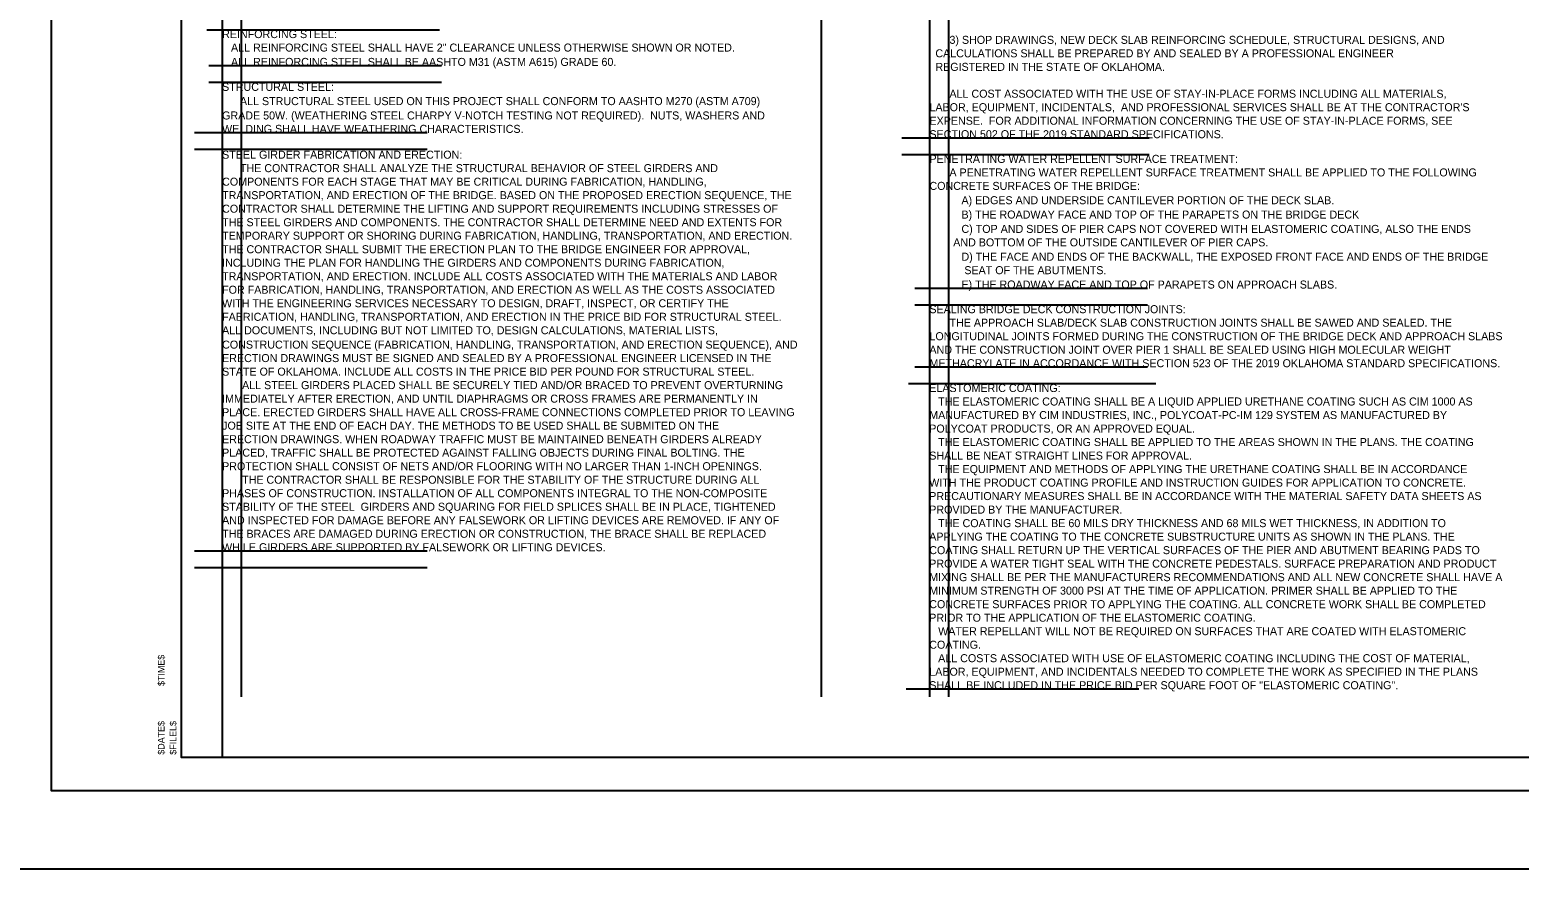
# Model space of a CAD drawing. Extents: x 12306 to 12361.5, y 578.9 to 640.4.
# Drawn here: x 12317.67 to 12340.01, y 612.91 to 625.5 of the extents above; entities that cross this region are included whole.
import ezdxf

# ---------------------------------------------------------------- set-up
doc = ezdxf.new("R2010")
doc.units = 0
for name, color, linetype in [('SHT_Plot_Shape_Full', 7, 'Continuous'), ('SHT_Plot_Shape_Half', 7, 'Continuous'), ('SHT_Plot_Stamp', 7, 'Continuous'), ('SHT_Sheet_Border', 7, 'Continuous'), ('T', 7, 'Continuous')]:
    doc.layers.add(name, color=color, linetype=linetype)

# ---------------------------------------------------------------- blocks, each defined once
blk = doc.blocks.new('Stamp_Plot_Stamp')
at = {"layer": 'SHT_Plot_Stamp'}
for s, p in [('$TIME$', (8.01, 7.43)), ('$DATE$', (8.01, 2.56)), ('$FILEL$', (8.85, 2.56))]:
    blk.add_text(s, height=0.472, rotation=90, dxfattribs=at).set_placement(p)

msp = doc.modelspace()

# ---------------------------------------------------------------- linework, layer by layer
at = {"layer": 'Defpoints'}
for p, q in [((12320.557, 635.145), (12320.557, 614.587)), ((12320.841, 635.145), (12320.841, 615.495)), ((12329.542, 635.145), (12329.542, 615.495)), ((12331.165, 635.145), (12331.165, 615.495)), ((12331.45, 635.145), (12331.45, 615.495)), ((12323.819, 625.494), (12320.33, 625.494)), ((12323.847, 624.957), (12320.358, 624.957)), ((12323.847, 624.707), (12320.358, 624.707)), ((12323.633, 623.953), (12320.144, 623.953)), ((12334.242, 623.873), (12330.752, 623.873)), ((12334.458, 623.873), (12330.969, 623.873)), ((12323.633, 623.703), (12320.144, 623.703)), ((12334.242, 623.623), (12330.752, 623.623)), ((12334.458, 623.623), (12330.969, 623.623)), ((12334.436, 621.619), (12330.946, 621.619)), ((12334.436, 621.369), (12330.946, 621.369)), ((12334.436, 620.439), (12330.946, 620.439)), ((12334.34, 620.189), (12330.85, 620.189)), ((12334.436, 620.189), (12330.946, 620.189)), ((12334.562, 620.189), (12331.072, 620.189)), ((12323.633, 617.68), (12320.144, 617.68)), ((12323.633, 617.43), (12320.144, 617.43)), ((12334.307, 615.611), (12330.817, 615.611))]:
    msp.add_line(p, q, dxfattribs=at)
at = {"layer": 'SHT_Plot_Shape_Full'}
msp.add_lwpolyline([(12316.36, 636.912), (12352.36, 636.912), (12352.36, 612.912), (12316.36, 612.912)], close=True, dxfattribs=at)
at = {"layer": 'SHT_Plot_Shape_Half'}
msp.add_lwpolyline([(12317.998, 636.087), (12351.998, 636.087), (12351.998, 614.087), (12317.998, 614.087)], close=True, dxfattribs=at)
at = {"layer": 'SHT_Sheet_Border'}
msp.add_lwpolyline([(12351.448, 614.587), (12319.948, 614.587), (12319.948, 635.587), (12351.448, 635.587)], close=True, dxfattribs=at)

# ---------------------------------------------------------------- block references
at = {"layer": 'SHT_Plot_Stamp', "xscale": 0.21166666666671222, "yscale": 0.21166666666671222}
msp.add_blockref('Stamp_Plot_Stamp', (12317.998, 614.087), dxfattribs=at)

# ---------------------------------------------------------------- texts
at = {"layer": 'T'}
for s, p in [('REINFORCING STEEL:', (12320.557, 625.374)), ('   ALL REINFORCING STEEL SHALL HAVE 2" CLEARANCE UNLESS OTHERWISE SHOWN OR NOTED.', (12320.557, 625.172)), ('3) SHOP DRAWINGS, NEW DECK SLAB REINFORCING SCHEDULE, STRUCTURAL DESIGNS, AND', (12331.465, 625.288)), ('   ALL REINFORCING STEEL SHALL BE AASHTO M31 (ASTM A615) GRADE 60.', (12320.557, 624.957)), ('  CALCULATIONS SHALL BE PREPARED BY AND SEALED BY A PROFESSIONAL ENGINEER', (12331.165, 625.086)), ('  REGISTERED IN THE STATE OF OKLAHOMA.', (12331.165, 624.883)), ('STRUCTURAL STEEL:', (12320.557, 624.583)), ('ALL COST ASSOCIATED WITH THE USE OF STAY-IN-PLACE FORMS INCLUDING ALL MATERIALS, ', (12331.465, 624.48)), ('      ALL STRUCTURAL STEEL USED ON THIS PROJECT SHALL CONFORM TO AASHTO M270 (ASTM A709) ', (12320.557, 624.369)), ("LABOR, EQUIPMENT, INCIDENTALS,  AND PROFESSIONAL SERVICES SHALL BE AT THE CONTRACTOR'S ", (12331.165, 624.278)), ('GRADE 50W. (WEATHERING STEEL CHARPY V-NOTCH TESTING NOT REQUIRED).  NUTS, WASHERS AND ', (12320.557, 624.154)), ('EXPENSE.  FOR ADDITIONAL INFORMATION CONCERNING THE USE OF STAY-IN-PLACE FORMS, SEE ', (12331.165, 624.075)), ('WELDING SHALL HAVE WEATHERING CHARACTERISTICS.', (12320.557, 623.953)), ('SECTION 502 OF THE 2019 STANDARD SPECIFICATIONS.', (12331.165, 623.873)), ('STEEL GIRDER FABRICATION AND ERECTION:', (12320.557, 623.566)), ('      THE CONTRACTOR SHALL ANALYZE THE STRUCTURAL BEHAVIOR OF STEEL GIRDERS AND ', (12320.557, 623.364)), ('PENETRATING WATER REPELLENT SURFACE TREATMENT:', (12331.165, 623.503)), ('COMPONENTS FOR EACH STAGE THAT MAY BE CRITICAL DURING FABRICATION, HANDLING, ', (12320.557, 623.161)), ('CONCRETE SURFACES OF THE BRIDGE:', (12331.165, 623.098)), ('A PENETRATING WATER REPELLENT SURFACE TREATMENT SHALL BE APPLIED TO THE FOLLOWING ', (12331.465, 623.3)), ('TRANSPORTATION, AND ERECTION OF THE BRIDGE. BASED ON THE PROPOSED ERECTION SEQUENCE, THE ', (12320.557, 622.959)), ('A) EDGES AND UNDERSIDE CANTILEVER PORTION OF THE DECK SLAB.', (12331.645, 622.883)), ('CONTRACTOR SHALL DETERMINE THE LIFTING AND SUPPORT REQUIREMENTS INCLUDING STRESSES OF ', (12320.557, 622.756)), ('B) THE ROADWAY FACE AND TOP OF THE PARAPETS ON THE BRIDGE DECK', (12331.645, 622.668)), ('THE STEEL GIRDERS AND COMPONENTS. THE CONTRACTOR SHALL DETERMINE NEED AND EXTENTS FOR ', (12320.557, 622.553)), ('C) TOP AND SIDES OF PIER CAPS NOT COVERED WITH ELASTOMERIC COATING, ALSO THE ENDS ', (12331.645, 622.453)), ('TEMPORARY SUPPORT OR SHORING DURING FABRICATION, HANDLING, TRANSPORTATION, AND ERECTION. ', (12320.557, 622.351)), ('        AND BOTTOM OF THE OUTSIDE CANTILEVER OF PIER CAPS.', (12331.165, 622.251)), ('THE CONTRACTOR SHALL SUBMIT THE ERECTION PLAN TO THE BRIDGE ENGINEER FOR APPROVAL, ', (12320.557, 622.148)), ('D) THE FACE AND ENDS OF THE BACKWALL, THE EXPOSED FRONT FACE AND ENDS OF THE BRIDGE    ', (12331.645, 622.036)), ('TRANSPORTATION, AND ERECTION. INCLUDE ALL COSTS ASSOCIATED WITH THE MATERIALS AND LABOR ', (12320.557, 621.743)), ('INCLUDING THE PLAN FOR HANDLING THE GIRDERS AND COMPONENTS DURING FABRICATION, ', (12320.557, 621.946)), ('     SEAT OF THE ABUTMENTS.', (12331.465, 621.834)), ('FOR FABRICATION, HANDLING, TRANSPORTATION, AND ERECTION AS WELL AS THE COSTS ASSOCIATED ', (12320.557, 621.541)), ('E) THE ROADWAY FACE AND TOP OF PARAPETS ON APPROACH SLABS.', (12331.645, 621.619)), ('WITH THE ENGINEERING SERVICES NECESSARY TO DESIGN, DRAFT, INSPECT, OR CERTIFY THE ', (12320.557, 621.338)), ('FABRICATION, HANDLING, TRANSPORTATION, AND ERECTION IN THE PRICE BID FOR STRUCTURAL STEEL. ', (12320.557, 621.135)), ('SEALING BRIDGE DECK CONSTRUCTION JOINTS:', (12331.165, 621.249)), ('ALL DOCUMENTS, INCLUDING BUT NOT LIMITED TO, DESIGN CALCULATIONS, MATERIAL LISTS, ', (12320.557, 620.933)), ('THE APPROACH SLAB/DECK SLAB CONSTRUCTION JOINTS SHALL BE SAWED AND SEALED. THE ', (12331.465, 621.047)), ('CONSTRUCTION SEQUENCE (FABRICATION, HANDLING, TRANSPORTATION, AND ERECTION SEQUENCE), AND ', (12320.557, 620.718)), ('AND THE CONSTRUCTION JOINT OVER PIER 1 SHALL BE SEALED USING HIGH MOLECULAR WEIGHT ', (12331.165, 620.641)), ('LONGITUDINAL JOINTS FORMED DURING THE CONSTRUCTION OF THE BRIDGE DECK AND APPROACH SLABS ', (12331.165, 620.844)), ('ERECTION DRAWINGS MUST BE SIGNED AND SEALED BY A PROFESSIONAL ENGINEER LICENSED IN THE ', (12320.557, 620.516)), ('METHACRYLATE IN ACCORDANCE WITH SECTION 523 OF THE 2019 OKLAHOMA STANDARD SPECIFICATIONS.', (12331.165, 620.439)), ('STATE OF OKLAHOMA. INCLUDE ALL COSTS IN THE PRICE BID PER POUND FOR STRUCTURAL STEEL.', (12320.557, 620.313)), ('ALL STEEL GIRDERS PLACED SHALL BE SECURELY TIED AND/OR BRACED TO PREVENT OVERTURNING ', (12320.857, 620.11)), ('ELASTOMERIC COATING:', (12331.162, 620.067)), ('IMMEDIATELY AFTER ERECTION, AND UNTIL DIAPHRAGMS OR CROSS FRAMES ARE PERMANENTLY IN ', (12320.557, 619.908)), ('   THE ELASTOMERIC COATING SHALL BE A LIQUID APPLIED URETHANE COATING SUCH AS CIM 1000 AS ', (12331.162, 619.865)), ('PLACE. ERECTED GIRDERS SHALL HAVE ALL CROSS-FRAME CONNECTIONS COMPLETED PRIOR TO LEAVING ', (12320.557, 619.705)), ('MANUFACTURED BY CIM INDUSTRIES, INC., POLYCOAT-PC-IM 129 SYSTEM AS MANUFACTURED BY ', (12331.162, 619.662)), ('JOB SITE AT THE END OF EACH DAY. THE METHODS TO BE USED SHALL BE SUBMITED ON THE ', (12320.557, 619.503)), ('ERECTION DRAWINGS. WHEN ROADWAY TRAFFIC MUST BE MAINTAINED BENEATH GIRDERS ALREADY ', (12320.557, 619.3)), ('POLYCOAT PRODUCTS, OR AN APPROVED EQUAL.', (12331.162, 619.459)), ('PLACED, TRAFFIC SHALL BE PROTECTED AGAINST FALLING OBJECTS DURING FINAL BOLTING. THE ', (12320.557, 619.098)), ('   THE ELASTOMERIC COATING SHALL BE APPLIED TO THE AREAS SHOWN IN THE PLANS. THE COATING ', (12331.162, 619.257)), ('PROTECTION SHALL CONSIST OF NETS AND/OR FLOORING WITH NO LARGER THAN 1-INCH OPENINGS. ', (12320.557, 618.895)), ('SHALL BE NEAT STRAIGHT LINES FOR APPROVAL.', (12331.162, 619.054)), ('   THE EQUIPMENT AND METHODS OF APPLYING THE URETHANE COATING SHALL BE IN ACCORDANCE ', (12331.162, 618.852)), ('THE CONTRACTOR SHALL BE RESPONSIBLE FOR THE STABILITY OF THE STRUCTURE DURING ALL ', (12320.857, 618.692)), ('WITH THE PRODUCT COATING PROFILE AND INSTRUCTION GUIDES FOR APPLICATION TO CONCRETE. ', (12331.162, 618.649)), ('PHASES OF CONSTRUCTION. INSTALLATION OF ALL COMPONENTS INTEGRAL TO THE NON-COMPOSITE ', (12320.557, 618.49)), ('PRECAUTIONARY MEASURES SHALL BE IN ACCORDANCE WITH THE MATERIAL SAFETY DATA SHEETS AS ', (12331.162, 618.447)), ('STABILITY OF THE STEEL  GIRDERS AND SQUARING FOR FIELD SPLICES SHALL BE IN PLACE, TIGHTENED ', (12320.557, 618.287)), ('PROVIDED BY THE MANUFACTURER.', (12331.162, 618.244)), ('AND INSPECTED FOR DAMAGE BEFORE ANY FALSEWORK OR LIFTING DEVICES ARE REMOVED. IF ANY OF ', (12320.557, 618.085)), ('   THE COATING SHALL BE 60 MILS DRY THICKNESS AND 68 MILS WET THICKNESS, IN ADDITION TO ', (12331.162, 618.041)), ('THE BRACES ARE DAMAGED DURING ERECTION OR CONSTRUCTION, THE BRACE SHALL BE REPLACED ', (12320.557, 617.882)), ('APPLYING THE COATING TO THE CONCRETE SUBSTRUCTURE UNITS AS SHOWN IN THE PLANS. THE ', (12331.162, 617.839)), ('WHILE GIRDERS ARE SUPPORTED BY FALSEWORK OR LIFTING DEVICES.', (12320.557, 617.68)), ('COATING SHALL RETURN UP THE VERTICAL SURFACES OF THE PIER AND ABUTMENT BEARING PADS TO ', (12331.162, 617.636)), ('PROVIDE A WATER TIGHT SEAL WITH THE CONCRETE PEDESTALS. SURFACE PREPARATION AND PRODUCT ', (12331.162, 617.434)), ('MIXING SHALL BE PER THE MANUFACTURERS RECOMMENDATIONS AND ALL NEW CONCRETE SHALL HAVE A ', (12331.162, 617.231)), ('CONCRETE SURFACES PRIOR TO APPLYING THE COATING. ALL CONCRETE WORK SHALL BE COMPLETED ', (12331.162, 616.826)), ('MINIMUM STRENGTH OF 3000 PSI AT THE TIME OF APPLICATION. PRIMER SHALL BE APPLIED TO THE ', (12331.162, 617.029)), ('PRIOR TO THE APPLICATION OF THE ELASTOMERIC COATING.', (12331.162, 616.623)), ('   WATER REPELLANT WILL NOT BE REQUIRED ON SURFACES THAT ARE COATED WITH ELASTOMERIC ', (12331.162, 616.421)), ('COATING.', (12331.162, 616.218)), ('   ALL COSTS ASSOCIATED WITH USE OF ELASTOMERIC COATING INCLUDING THE COST OF MATERIAL, ', (12331.162, 616.016)), ('LABOR, EQUIPMENT, AND INCIDENTALS NEEDED TO COMPLETE THE WORK AS SPECIFIED IN THE PLANS ', (12331.162, 615.813)), ('SHALL BE INCLUDED IN THE PRICE BID PER SQUARE FOOT OF "ELASTOMERIC COATING".', (12331.162, 615.611))]:
    msp.add_text(s, height=0.12, dxfattribs=at).set_placement(p)

doc.saveas('drawing.dxf')
